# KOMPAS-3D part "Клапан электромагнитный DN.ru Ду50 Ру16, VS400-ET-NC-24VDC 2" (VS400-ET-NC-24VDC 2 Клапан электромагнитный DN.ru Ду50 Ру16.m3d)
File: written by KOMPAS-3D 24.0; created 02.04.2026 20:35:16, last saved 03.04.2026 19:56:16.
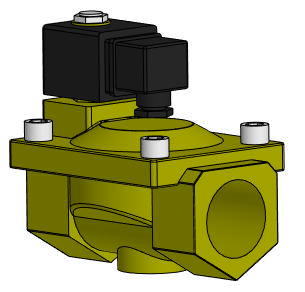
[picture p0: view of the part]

Document properties: Автор: artio; Полное имя файла: C:\Users\artio\OneDrive\Рабочий стол\Клапан электромагнитный DN.ru\VS400-ET-NC\VS400-ET-NC-24VDC 2 Клапан электромагнитный DN.ru Ду50 Ру16.m3d

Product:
- Body: Тело 1  | qty 1
    Масса: 7.119215
- Part/product: Клапан электромагнитный DN.ru Ду50 Ру16  | designation VS400-ET-NC-24VDC 2
    Масса: 3.509
    Раздел спецификации: Прочие изделия
    Примечание: D130-04724
    additional columns: ef56311e-7521-43dc-8291-0e6108b3d81d; VS400-ET-NC-220VAC 2; artio; c; Шероховатость не задана; Да

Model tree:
1. Операция без истории:1

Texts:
  VS400-ET-NC-24VDC 2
